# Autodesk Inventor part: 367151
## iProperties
Created: 2006-10
Part Number: 367151
Material: 8.8 vz
Description: Zylinderschraube
Vendor: Autodesk Inc.
Document SubType Name: Modeling
Standard: DIN 912
Designer: I.Baliuc
Standards Organization: DIN
Language: de-DE
Size Designation: M5 x 25
Categories: <MemberInstance Version="R10.0.0"><Categories><Category DisplayName="Schrauben" InternalName="e4da775c-781d-43d5-af7c-5136215cf5a6" Mnemonic="FSTN"><Category Di
Density: 7.85 g/cm^3
Abmessung: M5 x 25
Author: T.Messerschmitt
Comments: DIN 912 - M5 x 25
Revision Number: 367151
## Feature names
1. Körper [Revolution]
2. Loch [Extrusion]
3. Rundung1 [Fillet]
4. Fase1 [Chamfer]
